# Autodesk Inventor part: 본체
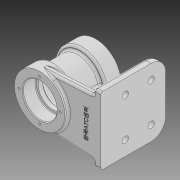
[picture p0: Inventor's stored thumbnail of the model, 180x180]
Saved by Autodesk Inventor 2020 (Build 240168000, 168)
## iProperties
Created: 2024-02
Part Number: 본체
Material: 일반
Document SubType Name: Modeling
Designer: oem
Density: 1 g/cm^3
Appearance: 기본값
Author: oem
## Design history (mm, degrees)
sketch "스케치1"
  geometry: C1 r 35 at (0, 0); C2 r 28.5 at (0, 0); 1 further point
  constraints: 2 centre point, 2 coincident
  dimensions: "d0" = 70 diameter of C1; "d1" = 57 diameter of C2
extrude "돌출1" new body sketch "스케치1" stored distance "d2" = 34; taper "d3" = 0 deg
sketch "스케치2"
  geometry: C1 r 28.5 at (0, 0) reference; C2 r 35 at (0, 0)
  constraints: 1 centre point, 1 coincident
  dimensions: "d4" = 70 diameter of C2
extrude "돌출2" join sketch "스케치2" distance "d5" = 22; taper "d6" = 0 deg
sketch "스케치3"
  geometry: C1 r 28.5 at (0, 0) reference; C2 r 35 at (0, 0)
  constraints: 1 centre point, 1 coincident
extrude "돌출3" join sketch "스케치3" distance "d7" = 22; taper "d8" = 0 deg
node "작업 평면1"
sketch "스케치4"
  geometry: L1 (70, -47)-(80, -47); L2 (80, -47)-(80, 47); L3 (80, 47)-(70, 47); L4 (70, 47)-(70, -47); L5 (70, -47)-(80, 47); L6 (80, -47)-(70, 47); 2 further points
  constraints: 12 end point, 2 midpoint, 2 parallel, 1 horizontal, 1 perpendicular
  dimensions: "d10" = 10 distance of L3.end L2.end; "d11" = 94 distance of L2.end L1.end; "d12" = 80 distance from line of point (0, 0) L2
extrude "돌출4" join sketch "스케치4" distance "d13" = 90; taper "d14" = 0 deg
sketch "스케치5"
  geometry: L1 (0, 94)-(0, 0) reference; L2 (0, 94)-(-90, 94) reference; L3 (-90, 0)-(-90, 94) reference; L4 (0, 0)-(-90, 0) reference; L5 (0, 0)-(0, 94) reference; L6 (0, 42)-(-78, 42); L7 (-78, 42)-(-78, 52); L8 (-78, 52)-(0, 52); L9 (0, 52)-(0, 42); 1 further point
  constraints: 8 end point, 2 parallel, 1 horizontal, 1 perpendicular, 1 point on line
  dimensions: "d15" = 78 distance of L7.end L8.end; "d16" = 10 distance of L6.end L7.end; "d17" = 5 distance from line of point (-34, 47) L8
sketch "스케치6"
  geometry: L1 (-28.5, 17)-(-35, 17) reference; L2 (-35, 17)-(-35, 39) reference; L3 (-35, 39)-(35, 39) reference; L4 (35, 39)-(35, 17) reference; L5 (35, 17)-(28.5, 17) reference; L6 (28.5, 17)-(28.5, -17) reference; L7 (28.5, -17)-(35, -17) reference; L8 (35, -17)-(35, -39) reference; L9 (35, -39)-(-35, -39) reference; L10 (-35, -39)-(-35, -17) reference; L11 (-35, -17)-(-28.5, -17) reference; L12 (-28.5, -17)-(-28.5, 17) reference; L13 (-70, 34)-(-70, -56) reference; L14 (-70, -56)-(-80, -56) reference; L15 (-80, -56)-(-80, 34) reference; L16 (-80, 34)-(-70, 34) reference; L17 (-70, 34)-(-80, 34) reference; L18 (-70, 34)-(-28.5, 34); L19 (-70, 34)-(-70, -56) reference; L20 (-70, -44)-(-28.5, -28.895); L21 (-70, -44)-(-21.567, -44); L22 (-28.5, -28.895)-(-28.5, 34); L23 (-70, 34)-(-70, -44); 4 further points
  constraints: 10 end point, 2 horizontal, 2 point on line, 1 collinear
  dimensions: "d18" = 20 deg angle of L21 L20; "d19" = 12 distance of L13.end L20.start
extrude "돌출5" join sketch "스케치6" stored distance "d20" = 10; taper "d21" = 0 deg
sketch "스케치7"
  geometry: L1 (70, 47)-(70, 5) reference; L2 (70, 39)-(-1.969, 34.945); 2 further points
  constraints: 2 end point, 1 point on line, 5 other
  dimensions: "d22" = 8 distance of L1.start L2.start
feature "리브1" sketch "스케치7" dims "d24" = 1, "d25" = 10, "d26" = 0, "d27" = 0, "d28" = 1, "d29" = 1
sketch "스케치8"
  geometry: L1 (90, 94)-(0, 94) reference; L2 (90, 8)-(90, 0) reference; L3 (90, 94)-(90, 86) reference; L4 (0, 94)-(0, 0) reference; L5 (0, 47)-(90, 47); L6 (90, 0)-(90, 94) reference; L7 (90, 0)-(0, 0) reference; C1 r 10 at (20, 74); C2 r 4.5 at (20, 74); C3 r 4.5 at (20, 20); C4 r 10 at (20, 20); C5 r 4.5 at (56, 74); C6 r 10 at (56, 74); C7 r 4.5 at (56, 20); C8 r 10 at (56, 20); 1 further point
  constraints: 8 centre point, 4 coincident, 2 end point, 2 midpoint, 2 symmetric about line, 2 other
  dimensions: "d30" = 20 diameter of C1; "d31" = 9 diameter of C2; "d32" = 20 distance from line of L1 C1.centre; "d34" = 70 distance from line of L3 C1.centre; "d35" = 70 distance from line of L6 C3.centre (derived); "d36" = 20 diameter of C6; "d37" = 9 diameter of C5; "d38" = 34 distance from line of L6 C6.centre; "d39" = 34 distance from line of L2 C7.centre; "d40" = 36 distance of C5.centre C1.centre; "d41" = 36 distance of C3.centre C8.centre
extrude "돌출6" cut sketch "스케치8" extent not by distance; stored distance "d42" = 92.271; taper "d43" = 0 deg
extrude "돌출7" join sketch "스케치8" distance "d44" = 3; taper "d45" = 0 deg
fillet "모깎기1" dims "d46" = 20
node "작업 평면2"
sketch "스케치9"
  geometry: C1 r 6 at (0, 0); 1 further point
  constraints: 1 centre point, 1 coincident
  dimensions: "d48" = 12 diameter of C1
extrude "돌출8" join sketch "스케치9" distance "d49" = 6; taper "d50" = 0 deg
sketch "스케치10"
  geometry: L1 (-28.5, 17)-(-28.5, -17) reference; L2 (35, -17)-(35, -39) reference; L3 (35, -39)-(-35, -39) reference; L4 (-35, -39)-(-35, -31.261) reference; L5 (-35, -31.261)-(-70, -44) reference; L6 (-70, -44)-(-70, -56) reference; L7 (-70, -56)-(-80, -56) reference; L8 (-80, -56)-(-80, 34) reference; L9 (-80, 34)-(-35, 34) reference; L10 (-35, 34)-(-35, 39) reference; L11 (-35, 39)-(35, 39) reference; L12 (35, 39)-(35, 17) reference; L13 (35, 17)-(28.5, 17) reference; L14 (28.5, 17)-(28.5, 6) reference; L15 (28.5, 6)-(31.5, 6) reference; L16 (31.5, 6)-(31.5, -6) reference; L17 (31.5, -6)-(28.5, -6) reference; L18 (28.5, -6)-(28.5, -17) reference; L19 (28.5, -17)-(35, -17) reference; L20 (35, 39)-(-35, 39) reference; L21 (0, 39)-(0, -39); L22 (23.5, 15)-(0, 15); L23 (0, -15)-(23.5, -15); L24 (23.5, -15)-(23.5, 15); L25 (23.5, 39)-(23.5, 21); L26 (23.5, 21)-(0, 21); L27 (23.5, 39)-(0, 39); L28 (20, 21)-(20, 15); L29 (31.5, 0)-(0, 0); L30 (23.5, -39)-(23.5, -21); L31 (23.5, -21)-(0, -21); L32 (23.5, -39)-(0, -39); L33 (20, -15)-(20, -21); 3 further points
  constraints: 26 end point, 8 point on line, 4 perpendicular, 3 midpoint, 3 symmetric about line, 2 horizontal, 1 collinear, 1 parallel
  dimensions: "d53" = 23.5 distance of L22.end L22.start; "d54" = 18 distance of L25.start L25.end; "d55" = 40 diameter of L28 L21; "d56" = 47 diameter of L30.start L21; "d57" = 40 diameter of L33 L21
revolve "회전1" sketch "스케치10" stored, may be unused: angle "d58" = 90 deg
fillet "모깎기2" dims "d59" = 3
fillet "모깎기3" dims "d60" = 1
chamfer "모따기1" distance "d61" = 1; stored, may be unused: second distance "d62" = 2, angle "d63" = 45 deg
sketch "스케치11"
  geometry: C1 r 24.5 at (0, 0) reference; A1 r 28.5 centre (0, 0) between (-28.5, 0) and (28.5, 0); A2 r 28.5 centre (0, 0) between (-28.5, 0) and (0, 28.5) reference; 2 further points
  constraints: 4 point on circle, 1 centre point, 1 coincident
  dimensions: "d64" = 57 diameter of A1
hole "구멍1" sketch "스케치11" at (-28.5, 0), (0, 28.5), (0, -28.5), (28.5, 0) diameter "d65" = 3.242; stored, may be unused: countersink angle "d69" = 90 deg, drill point angle "d71" = 118 deg; dims "d66" = 8, "d67" = 10, "d68" = 3, "d70" = 10
sketch "스케치12"
  geometry: C1 r 6 at (0, 0) reference; 1 further point
  constraints: 1 coincident
hole "구멍2" sketch "스케치12" at (0, 0) diameter "d72" = 5.1881; stored, may be unused: countersink angle "d76" = 90 deg, drill point angle "d78" = 0 deg; dims "d73" = 16, "d74" = 7, "d75" = 2, "d77" = 16
sketch "스케치13"
  geometry: L1 (-25.685, 24.121)-(-32.628, 24.121); L2 (-32.628, 24.121)-(-32.628, -24.121); L3 (-32.628, -24.121)-(-25.685, -24.121); L4 (-25.685, -24.121)-(-25.685, 24.121); L5 (-25.685, 24.121)-(-32.628, -24.121); L6 (-32.628, 24.121)-(-25.685, -24.121); 2 further points
  constraints: 12 end point, 2 midpoint, 2 parallel, 1 horizontal, 1 perpendicular
extrude "돌출9" join sketch "스케치13" stored distance "d83" = 10; taper "d84" = 0 deg
fillet "모깎기12" dims "d89" = 3
fillet "모깎기13" dims "d90" = 3
fillet "모깎기14" dims "d91" = 3
fillet "모깎기15" dims "d92" = 3
fillet "모깎기16" dims "d93" = 3
fillet "모깎기17" dims "d94" = 3
fillet "모깎기18" dims "d95" = 3
fillet "모깎기19" dims "d96" = 3
fillet "모깎기20" dims "d97" = 3
fillet "모깎기21" dims "d98" = 3
fillet "모깎기22" dims "d99" = 3
fillet "모깎기23" dims "d100" = 3
sketch "스케치14"
  geometry: L1 (80, -44)-(80, 44) reference; L2 (18.661, 33.102)-(67.338, 35.845) reference; L3 (18.661, -33.102)-(67, -35.826) reference; L4 (60, -35.432)-(60, 35.432); L5 (80, 27)-(80, -27) reference; L6 (80, 0)-(39.026, 0); L7 (56.737, -21.086)-(56.737, 20.393); L8 (56.737, 20.393)-(62.741, 20.393); L9 (62.741, 20.393)-(62.741, -21.086); L10 (62.741, -21.086)-(56.737, -21.086); A1 r 38 centre (1.026, 0) between (38.973, -2) and (38.973, 2) reference
  constraints: 4 end point, 2 point on line, 1 horizontal, 1 midpoint, 1 point on circle, 1 vertical, 2 other
  dimensions: "d101" = 20 distance between parallel lines of L1 L4
feature "엠보싱1" sketch "스케치14" dims "d0" = 70, "d1" = 57, "d102" = 0.5, "d103" = 0
node "솔리드1"
mirror "미러1"
mirror "미러2"
node "절단 모서리 투영1"
node "절단 모서리 투영2"
feature "A9D066F2-1C7D-4E18-AEED-F7BC21143FA4" dims "d65" = 3.242, "d66" = 8, "d67" = 10, "d68" = 3, "d69" = 90 deg, "d70" = 10, "d71" = 118 deg
other parameters: "d9" = -5, "d47" = -31.5
